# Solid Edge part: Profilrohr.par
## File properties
Username: bmolnar
Dokumentum tartalom típus: 0
Author: bmolnar
Last saved by: bmolnar
Revision: 82
Sűrűség: 0,000 kg/m^3
Pontosság: 0,990
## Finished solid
Body 1: solid body, 59 faces, 170 edges, 112 vertices.
  Faces by surface: plane 30, cylinder 29
  Edges by curve: line 112, circle 58
Bounding box of the edges (mm): 40.000 x 54.000 x 40.000, from (-20, -9.5, -20) to (20, 44.5, 20).
Cylindrical faces by radius (mm): R0.2 x12, R0.5 x12, R5 x4, R12.5 x1
Planar faces by outward normal: +x 7, +y 1, +z 7, -x 7, -y 1, -z 7
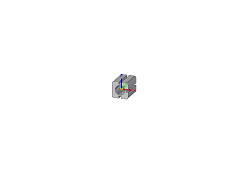
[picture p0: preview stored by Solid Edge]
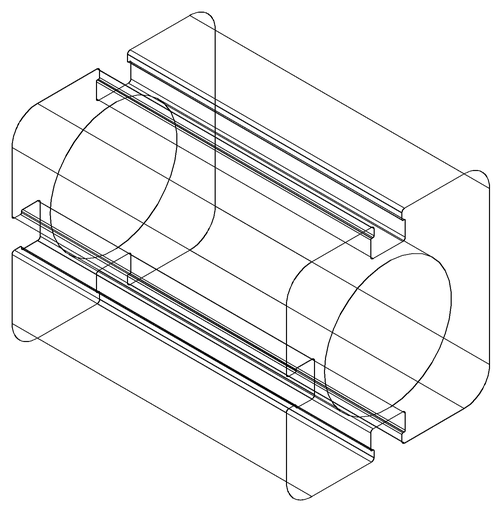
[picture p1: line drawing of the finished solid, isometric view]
